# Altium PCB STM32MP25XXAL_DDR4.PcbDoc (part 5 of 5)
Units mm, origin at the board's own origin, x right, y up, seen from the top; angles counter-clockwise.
Board outline 125 x 95 mm, 6 copper layers (Top Layer, Signal Layer 1, Signal Layer 2, Signal Layer 3, Signal Layer 4, Bottom Layer), stack 1.403 mm thick; 220 components, 316 nets, 1103 pads, 939 vias.
Unrouted connection lines stored in the file: 5.
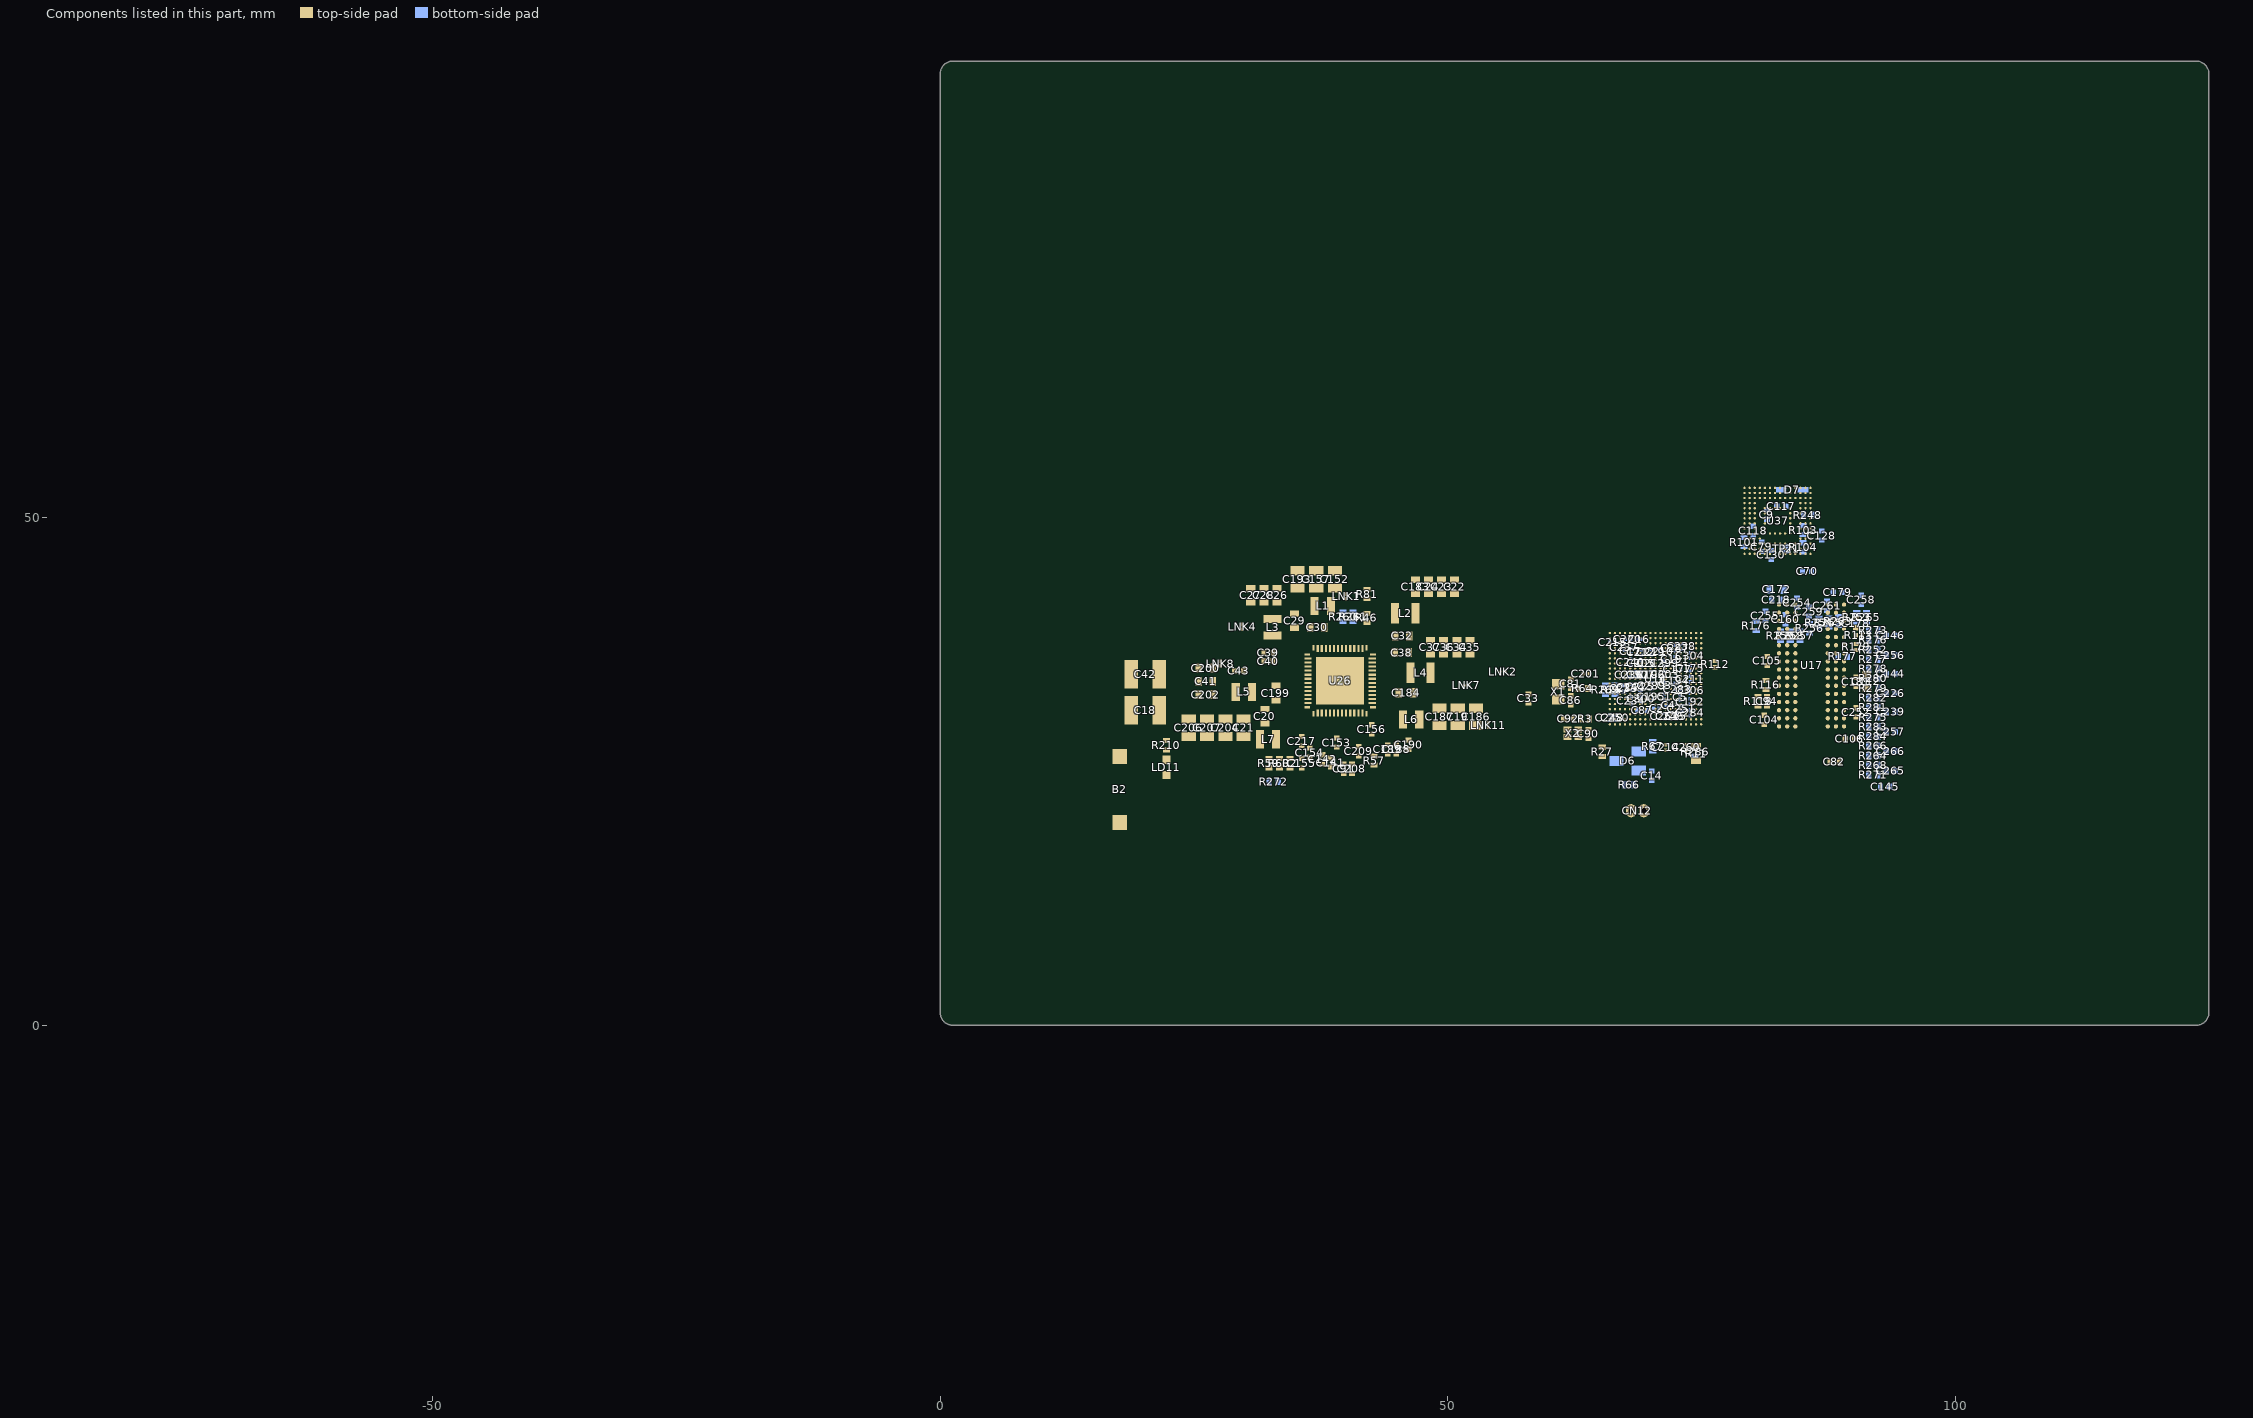
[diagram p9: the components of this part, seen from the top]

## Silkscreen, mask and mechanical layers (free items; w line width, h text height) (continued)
M20-Top Sheet Box:
  circle w0.254: c105.427,-32.893 r1.3
  region: 90.949,-33.986 80.193,-33.986 81.186,-31.493 89.044,-31.493 89.493,-30.734 91.701,-33.282
  region: 104.952,-25.657 89.425,-25.657 88.731,-27.432 87.52,-28.657 86.123,-26.797 86.123,-25.146 87.266,-23.749 88.702,-23.371 104.952,-23.371
  lines w0.254: 81.186,-31.493 89.978,-31.493 86.912,-27.956 cw(c88.716,-26.012) 88.956,-23.371 105.72,-23.371 104.958,-25.657 ; 84.5,-23.124 cw(c86.926,-24.094) 87.163,-21.492 ; 84.539,-23.091 80.193,-33.986 99.515,-33.986 ccw(c99.764,-31.252) 102.313,-32.272 ; 86.279,-27.026 91.701,-33.282 ; 86.533,-27.026 91.838,-33.147 ; 86.533,-26.772 91.838,-32.893 ; 86.631,-25.657 99.624,-25.657 ; 86.66,-26.645 91.965,-32.766 ; 86.787,-26.518 92.092,-32.639 ; 86.914,-26.391 92.219,-32.512 ; 87.041,-26.264 92.346,-32.385 ; 87.096,-24.312 92.401,-30.433 ; 87.164,-21.492 106.614,-21.492 102.314,-32.269 ; 87.168,-26.137 92.418,-32.195 ; 87.168,-25.883 92.473,-32.004 ; 87.168,-25.629 92.473,-31.75 ; 87.168,-24.74 92.473,-30.861 ; 87.295,-25.502 92.6,-31.623 ; 87.295,-25.121 92.6,-31.242 ; 88.667,-31.507 ccw(c88.772,-30.972) 89.069,-30.515 ; 89.753,-25.643 ccw(c89.727,-26.211) 89.397,-26.673 91.762,-29.401 cw(c89.958,-31.345) 90.691,-33.894 ; 96.034,-33.782 98.924,-25.403 ; 96.257,-33.732 99.126,-25.412 ; 96.384,-33.732 99.253,-25.412 ; 96.638,-33.732 99.507,-25.412 ; 96.892,-33.732 99.761,-25.412 ; 97.146,-33.732 100.015,-25.412 ; 97.4,-33.732 100.269,-25.412 ; 97.654,-33.732 100.523,-25.412 ; 97.908,-33.732 100.777,-25.412 ; 98.162,-33.732 101.031,-25.412 ; 98.37,-33.782 101.26,-25.403 ; 101.26,-25.657 104.952,-25.657 ; 104.284,-25.654 105.046,-23.368 ; 104.45,-25.657 105.212,-23.371 ; 104.704,-25.657 105.466,-23.371
  lines w0.3: 18.423,-32.872 78.423,-32.872 ; 18.423,-27.872 78.423,-27.872 ; 18.423,-22.872 78.423,-22.872 ; 58.423,-37.872 58.423,-22.872 ; 78.423,-37.872 78.423,-17.872 ; 96.034,-33.782 98.37,-33.782 ; 18.423,-37.872 108.423,-37.872 108.423,-17.872 18.423,-17.872 18.423,-37.872
M21-Bottom Sheet Box:
  circle w0.254: c21.598,-32.885 r1.3
  region: 22.073,-25.649 37.6,-25.649 38.295,-27.424 39.505,-28.649 40.902,-26.789 40.902,-25.138 39.759,-23.741 38.323,-23.363 22.073,-23.363
  region: 36.076,-33.978 46.832,-33.978 45.839,-31.485 37.981,-31.485 37.533,-30.726 35.324,-33.274
  lines w0.254: 21.559,-23.363 22.321,-25.649 ; 21.813,-23.363 22.575,-25.649 ; 21.979,-23.36 22.741,-25.646 ; 22.067,-25.649 21.305,-23.363 38.069,-23.363 cw(c38.309,-26.004) 40.113,-27.948 37.047,-31.485 45.839,-31.485 ; 22.073,-25.649 25.766,-25.649 ; 24.711,-32.261 20.412,-21.484 39.861,-21.484 ; 24.712,-32.264 ccw(c27.261,-31.244) 27.51,-33.978 46.832,-33.978 42.486,-23.083 ; 25.766,-25.395 28.655,-33.774 ; 25.994,-25.404 28.863,-33.724 ; 26.248,-25.404 29.117,-33.724 ; 26.502,-25.404 29.371,-33.724 ; 26.756,-25.404 29.625,-33.724 ; 27.01,-25.404 29.879,-33.724 ; 27.264,-25.404 30.133,-33.724 ; 27.401,-25.649 40.394,-25.649 ; 27.518,-25.404 30.387,-33.724 ; 27.772,-25.404 30.641,-33.724 ; 27.899,-25.404 30.768,-33.724 ; 28.101,-25.395 30.991,-33.774 ; 34.425,-31.615 39.73,-25.494 ; 34.425,-31.234 39.73,-25.113 ; 34.552,-31.996 39.857,-25.875 ; 34.552,-31.742 39.857,-25.621 ; 34.552,-30.853 39.857,-24.732 ; 34.607,-32.187 39.857,-26.129 ; 34.625,-30.425 39.93,-24.304 ; 34.679,-32.377 39.984,-26.256 ; 34.806,-32.504 40.111,-26.383 ; 34.933,-32.631 40.238,-26.51 ; 35.06,-32.758 40.365,-26.637 ; 35.187,-33.139 40.492,-27.018 ; 35.187,-32.885 40.492,-26.764 ; 35.324,-33.274 40.746,-27.018 ; 36.335,-33.886 cw(c37.067,-31.337) 35.264,-29.394 37.628,-26.665 ccw(c37.298,-26.203) 37.272,-25.635 ; 37.956,-30.507 ccw(c38.254,-30.964) 38.359,-31.499 ; 39.863,-21.484 cw(c40.099,-24.086) 42.525,-23.116
  lines w0.3: 28.655,-33.774 30.991,-33.774 ; 48.416,-37.864 48.416,-17.864 ; 48.416,-32.864 108.416,-32.864 ; 48.416,-27.864 108.416,-27.864 ; 48.416,-22.864 108.416,-22.864 ; 68.416,-37.864 68.416,-22.864 ; 18.416,-37.864 18.416,-17.864 108.416,-17.864 108.416,-37.864 18.416,-37.864

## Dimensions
1.27,0 to 1.27,95 on M2-Board Dimensions
0,93.73 to 125,93.73 on M2-Board Dimensions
